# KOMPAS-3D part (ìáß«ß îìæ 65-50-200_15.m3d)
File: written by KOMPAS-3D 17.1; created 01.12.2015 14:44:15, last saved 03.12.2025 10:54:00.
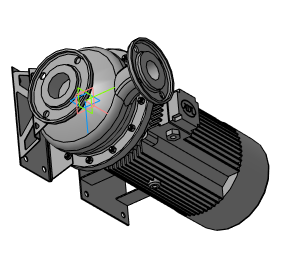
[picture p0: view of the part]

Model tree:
1. Операция без истории:3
